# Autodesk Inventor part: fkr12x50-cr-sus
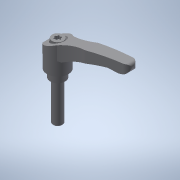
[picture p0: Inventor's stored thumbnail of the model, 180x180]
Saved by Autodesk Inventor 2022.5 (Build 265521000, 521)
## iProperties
Created: 2017-09
Part Number: fkr12x50-cr-sus
Material: 一般
Document SubType Name: Modeling
Designer: imaocorp
Density: 1 g/cm^3
Appearance: 既定
Author: imaocorp
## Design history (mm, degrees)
node "fkr12x50-cr-sus.x_t1"
node "fkr12x50-cr-sus"
node "Base1"
